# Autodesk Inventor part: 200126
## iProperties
Created: 2007-11
Part Number: 200126
Document SubType Name: Modeling
Designer: TH
Density: 8.08 g/cm^3
Mass: 46.0488 g
Surface Area: 57.2425 cm^2
Volume: 5.69911 cm^3
Material: Stainless Steel
Description: SPRING WIRE
Component Category: Lower Component
Author: TH
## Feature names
1. Sweep2
2. Sweep3
